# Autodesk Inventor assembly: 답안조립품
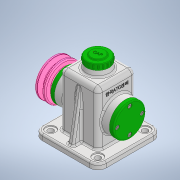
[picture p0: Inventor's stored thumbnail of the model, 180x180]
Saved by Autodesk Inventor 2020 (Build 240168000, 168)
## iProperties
Created: 2021-07
Part Number: 답안조립품
Document SubType Name: Assembly
Designer: Owner
Author: Owner
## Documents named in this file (14)
- C:\Users\Owner\Desktop\710715V1007\답안조립품.iam
- C:\Users\Owner\Desktop\710715V1007\본체.ipt
- C:\Users\Owner\Desktop\710715V1007\V-벨트풀리.ipt
- C:\Users\Owner\Desktop\710715V1007\뒤커버.ipt
- C:\Users\Owner\Desktop\710715V1007\멈춤링 15 x 1.ipt
- C:\Users\Owner\Desktop\710715V1007\베어링 15 x 35 x 11.ipt
- C:\Users\Owner\Desktop\710715V1007\볼트 M4 x 10.ipt
- C:\Users\Owner\Desktop\710715V1007\볼트 M6 x 12.ipt
- C:\Users\Owner\Desktop\710715V1007\상부캡.ipt
- C:\Users\Owner\Desktop\710715V1007\앞커버.ipt
- C:\Users\Owner\Desktop\710715V1007\오일실 15 25 7.ipt
- C:\Users\Owner\Desktop\710715V1007\와셔.ipt
- C:\Users\Owner\Desktop\710715V1007\축.ipt
- C:\Users\Owner\Desktop\710715V1007\키 5 x 5 x 14.ipt
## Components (1 placed, 1 different names)
1. V-벨트풀리:1
